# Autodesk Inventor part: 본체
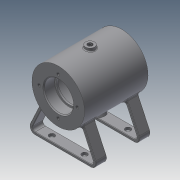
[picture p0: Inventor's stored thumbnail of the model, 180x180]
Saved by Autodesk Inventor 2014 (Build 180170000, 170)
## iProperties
Created: 2021-12
Part Number: 본체
Material: 일반
Document SubType Name: Modeling
Designer: dg
Density: 1 g/cm^3
Appearance: 기본값
Mass: 114.909 g
Surface Area: 354.971 cm^2
Volume: 114.909 cm^3
Author: dg
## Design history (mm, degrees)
sketch "스케치1"
  geometry: L1 (-35, 0)-(35, 0); L2 (-34, 16)-(-23.3, 16); L3 (-23, 15.7)-(-23, 14); L4 (-23, 14)-(-21, 14); L5 (-21, 14)-(-21, 18); L6 (-18, 21)-(18, 21); L7 (21, 18)-(21, 14); L8 (21, 14)-(23, 14); L9 (23, 14)-(23, 15.7); L10 (23.3, 16)-(34, 16); L11 (35, 17)-(35, 29); L12 (35, 29)-(-35, 29); L13 (-35, 29)-(-35, 17); L14 (35, 17)-(34, 16); L15 (-35, 17)-(-34, 16); A1 r 3 centre (-18, 18) between (-18, 21) and (-21, 18); A2 r 3 centre (18, 18) between (21, 18) and (18, 21); A3 r 0.3 centre (-23.3, 15.7) between (-23, 15.7) and (-23.3, 16); A4 r 0.3 centre (23.3, 15.7) between (23.3, 16) and (23, 15.7); 8 further points
  constraints: 30 end point, 12 point on line, 9 parallel, 8 point on circle, 8 tangent, 4 centre point, 3 collinear, 2 equal radius, 2 horizontal alignment, 2 vertical alignment, 1 coincident, 1 horizontal, 1 midpoint, 1 perpendicular, 1 vertical
  dimensions: "d0" = 70 distance of L1.start L1.end; "d1" = 42 distance of point (-21, 21) point (21, 21); "d2" = 12 distance of point (23, 16) point (35, 16); "d3" = 28 diameter of L7.end L1; "d4" = 32 diameter of L10 L1; "d5" = 42 diameter of L6 L1; "d6" = 58 diameter of L12 L1; "d7" = 3 radius of A1; "d8" = 0.3 radius of A3; "d9" = 1 distance of L11.start point (35, 16); "d10" = 1 distance of L10.end point (35, 16) (= d9); "d11" = 1 distance of L13.end point (-35, 16) (= d9); "d12" = 1 distance of L2.start point (-35, 16) (= d11)
revolve "회전1" sketch "스케치1" stored, may be unused: angle "d13" = 90 deg
sketch "스케치2"
  geometry: C1 r 17 at (0, 0) reference; C2 r 29 at (0, 0) reference; A1 r 21 centre (0, 0) between (0, 21) and (-21, 0); 2 further points
  constraints: 4 point on circle, 2 horizontal alignment, 2 vertical alignment, 1 centre point, 1 coincident
  dimensions: "d14" = 42 diameter of A1
hole "구멍1" sketch "스케치2" at (0, 21), (-21, 0), (0, -21), (21, 0) diameter "d15" = 3.242; stored, may be unused: countersink angle "d19" = 90 deg, drill point angle "d21" = 118 deg; dims "d16" = 8, "d17" = 4, "d18" = 2, "d20" = 10
node "작업 평면1"
sketch "스케치3"
  geometry: C1 r 5 at (0, 0); C2 r 1.5 at (0, 0); 2 further points
  constraints: 3 coincident, 2 centre point
  dimensions: "d23" = 10 diameter of C1; "d24" = 3 diameter of C2
extrude "돌출1" join sketch "스케치3" stored distance "d25" = 10; taper "d26" = 0 deg
hole "구멍2" sketch "스케치3" diameter "d27" = 5.188; stored, may be unused: countersink angle "d31" = 90 deg, drill point angle "d33" = 118 deg; dims "d28" = 6, "d29" = 4, "d30" = 2, "d32" = 8
extrude "돌출2" cut sketch "스케치3" stored distance "d34" = 10; taper "d35" = 0 deg
node "작업 평면2"
sketch "스케치4"
  geometry: L1 (5, 32)-(5, 28.566) reference; L2 (-5, 28.566)-(-5, 32) reference; L3 (-5, 32)-(-2.594, 32) reference; L4 (-2.594, 32)-(-2.594, 24) reference; L5 (-2.594, 24)-(-1.5, 23.343) reference; L6 (-1.5, 23.343)-(-1.5, 20.946) reference; L7 (1.5, 20.946)-(1.5, 23.343) reference; L8 (1.5, 23.343)-(2.594, 24) reference; L9 (2.594, 24)-(2.594, 32) reference; L10 (2.594, 32)-(5, 32) reference; L11 (0, 0)-(0, -29); L12 (0, 0)-(10.945, -30.07); A1 r 29 centre (0, 0) between (-5, 28.566) and (5, 28.566) reference; A2 r 21 centre (0, 0) between (-1.5, 20.946) and (1.5, 20.946) reference; 1 further point
  constraints: 4 end point, 1 point on circle
  dimensions: "d37" = 20 deg angle of L12 L11; "d38" = 32 distance of L11.start L12.end
  node "절단 모서리 투영1"
node "작업 평면3"
sketch "스케치5"
  geometry: C1 r 6 at (0, 0); 2 further points
  constraints: 2 coincident, 1 centre point
  dimensions: "d39" = 12 diameter of C1
extrude "돌출3" join sketch "스케치5" stored distance "d40" = 10; taper "d41" = 0 deg
hole "구멍3" sketch "스케치5" diameter "d42" = 5.188; stored, may be unused: countersink angle "d46" = 90 deg, drill point angle "d48" = 118 deg; dims "d43" = 6, "d44" = 4, "d45" = 2, "d47" = 8
node "작업 평면4"
sketch "스케치6"
  geometry: L1 (-22.743, -17.993)-(-40, -55); L2 (-40, -55)-(40, -55); L3 (40, -55)-(22.743, -17.993); L4 (20.574, -20.438)-(35.291, -52); L5 (35.291, -52)-(-35.291, -52); L6 (-35.291, -52)-(-20.574, -20.438); C1 r 16 at (0, 0) reference; A1 r 29 centre (0, 0) between (-22.743, -17.993) and (22.743, -17.993) reference; 1 further point
  constraints: 12 end point, 4 point on circle, 3 parallel, 1 equal length, 1 horizontal, 1 horizontal alignment
  dimensions: "d50" = 80 distance of L1.end L2.end; "d51" = 55 distance from line of L2 point (0, 0); "d52" = 65 deg angle of L2 L1; "d53" = 3 distance between parallel lines of L2 L5; "d54" = 3 distance between parallel lines of L3 L4; "d55" = 3 distance between parallel lines of L1 L6
extrude "돌출4" join sketch "스케치6" stored distance "d56" = 12; taper "d57" = 0 deg
fillet "모깎기1" dims "d58" = 6, "d59" = 3
fillet "모깎기2" dims "d60" = 0.5
fillet "모깎기3" dims "d61" = 3, "d62" = 1
sketch "스케치7"
  geometry: L1 (61.164, 48)-(0, 48) reference; L2 (0, 37)-(0, 48) reference; L3 (0, 37)-(61.164, 37) reference; L4 (61.164, 37)-(61.164, 48) reference; L5 (0, 0)-(61.164, 0) reference; L6 (61.164, -11)-(61.164, 0) reference; L7 (61.164, -11)-(0, -11) reference; L8 (0, -11)-(0, 0) reference; C1 r 3 at (12.582, 42.5); C2 r 3 at (48.582, 42.5); 2 further points
  constraints: 2 centre point, 2 horizontal alignment, 1 equal radius, 1 midpoint
  dimensions: "d63" = 36 distance of C2.centre C1.centre; "d64" = 6 diameter of C2; "d65" = 18 horizontal distance of point (30.582, 18.5) C1.centre
extrude "돌출5" cut sketch "스케치7" stored distance "d66" = 12; taper "d67" = 0 deg
node "작업 평면5"
sketch "스케치8"
  geometry: L1 (-35, -29)-(-35, 29) reference; 2 further points
  constraints: 2 coincident, 1 other
feature "엠보싱1" sketch "스케치8" dims "d0" = 70, "d1" = 42, "d2" = 12, "d3" = 28, "d4" = 32, "d5" = 42, "d6" = 58, "d7" = 3, "d8" = 0.3, "d9" = 1, "d10" = 1 (= d9), "d11" = 1 (= d9), "d12" = 1 (= d11), "d71" = 0.5, "d72" = 0
node "솔리드1"
mirror "대칭1"
mirror "대칭2"
mirror "대칭3"
node "절단 모서리 투영2"
node "절단 모서리 투영3"
other parameters: "d22" = 32, "d36" = -35, "d49" = -24, "d68" = -29
